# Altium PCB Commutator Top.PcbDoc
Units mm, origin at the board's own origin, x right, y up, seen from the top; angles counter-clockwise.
Board outline 60.27 x 62.49 mm, 2 copper layers (Top, Bottom); 20 components, 31 nets, 112 pads, 44 vias.
Unrouted connection lines stored in the file: 12.
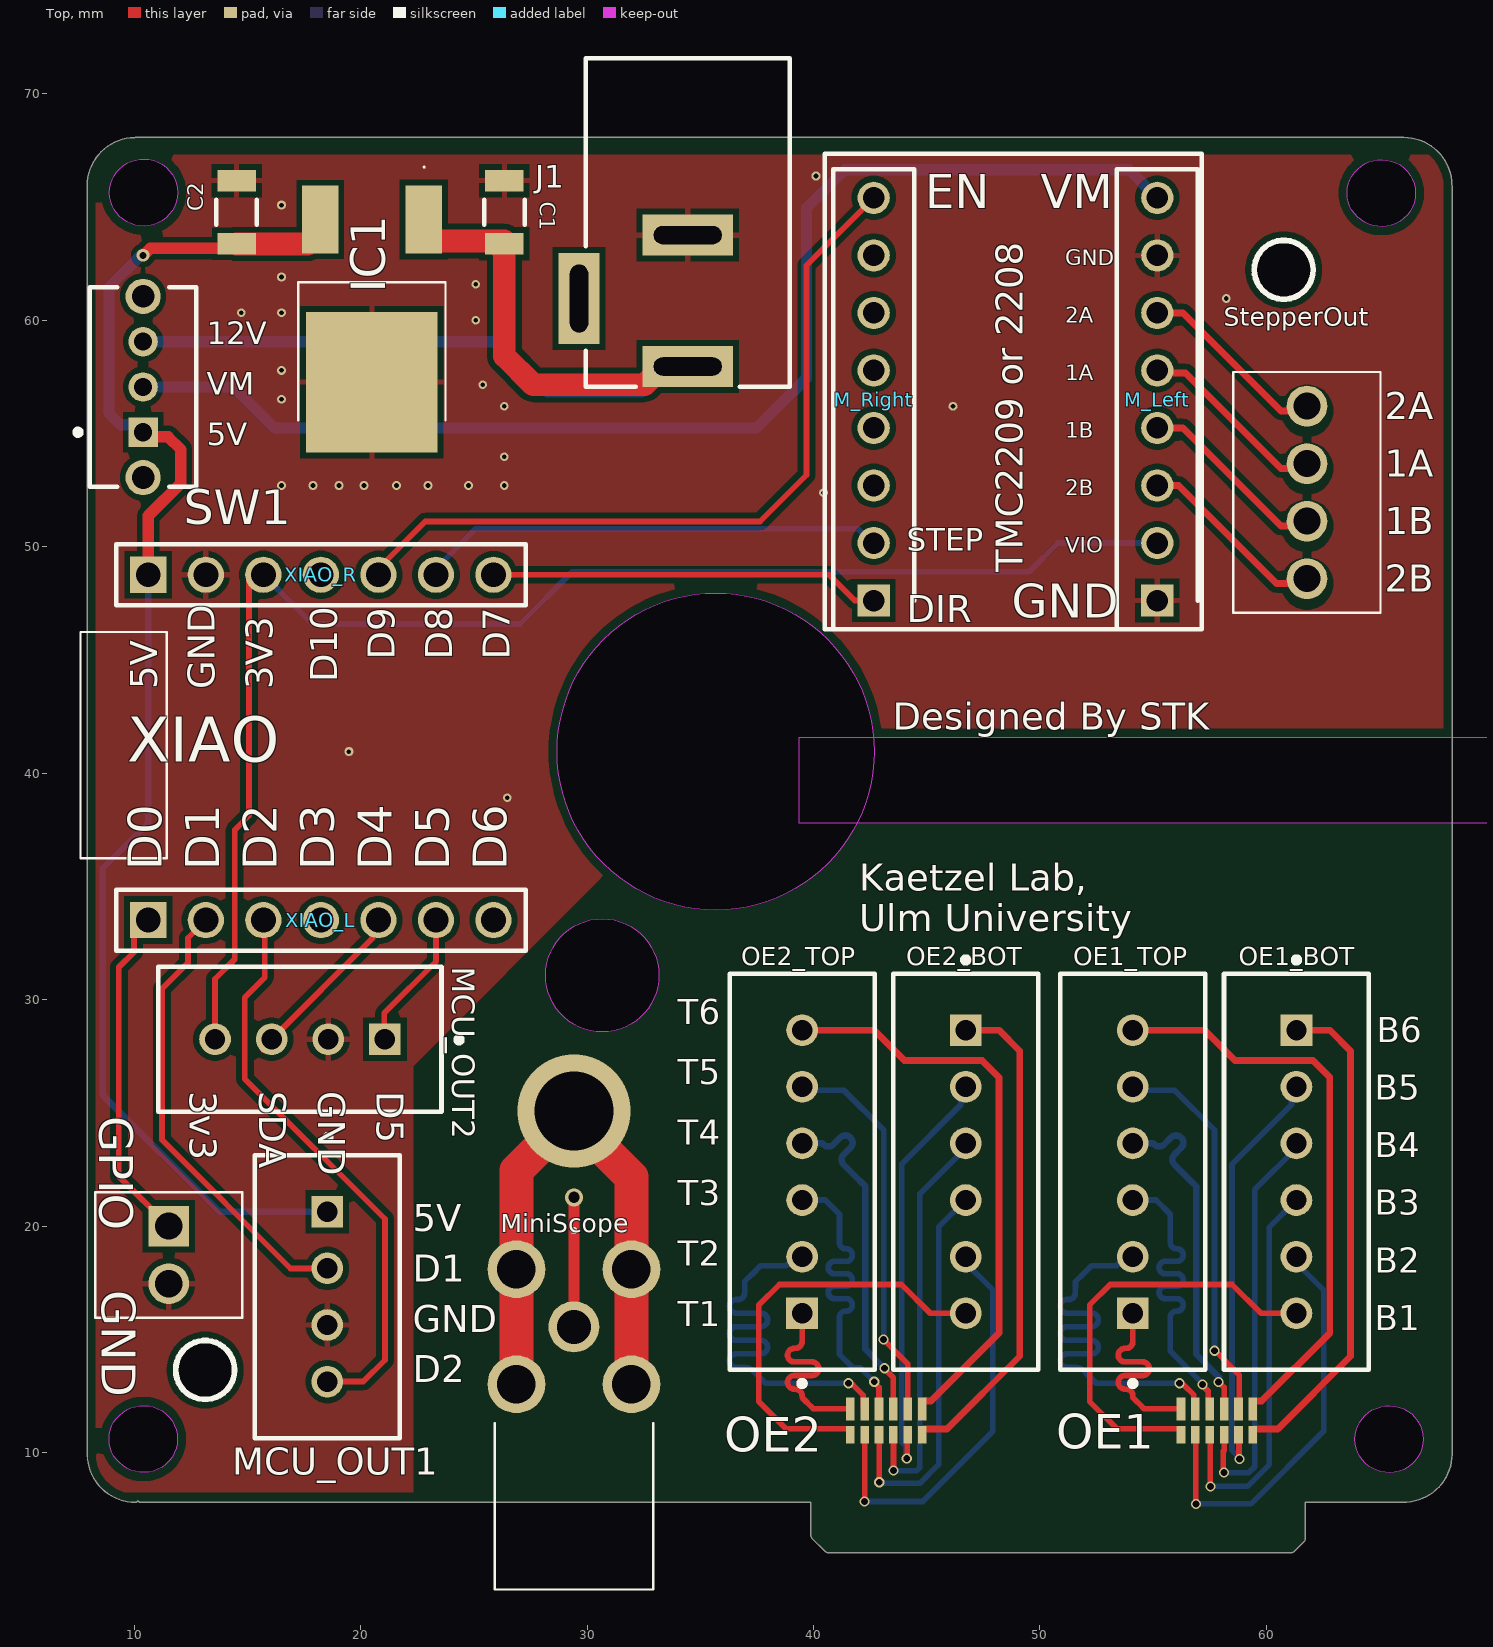
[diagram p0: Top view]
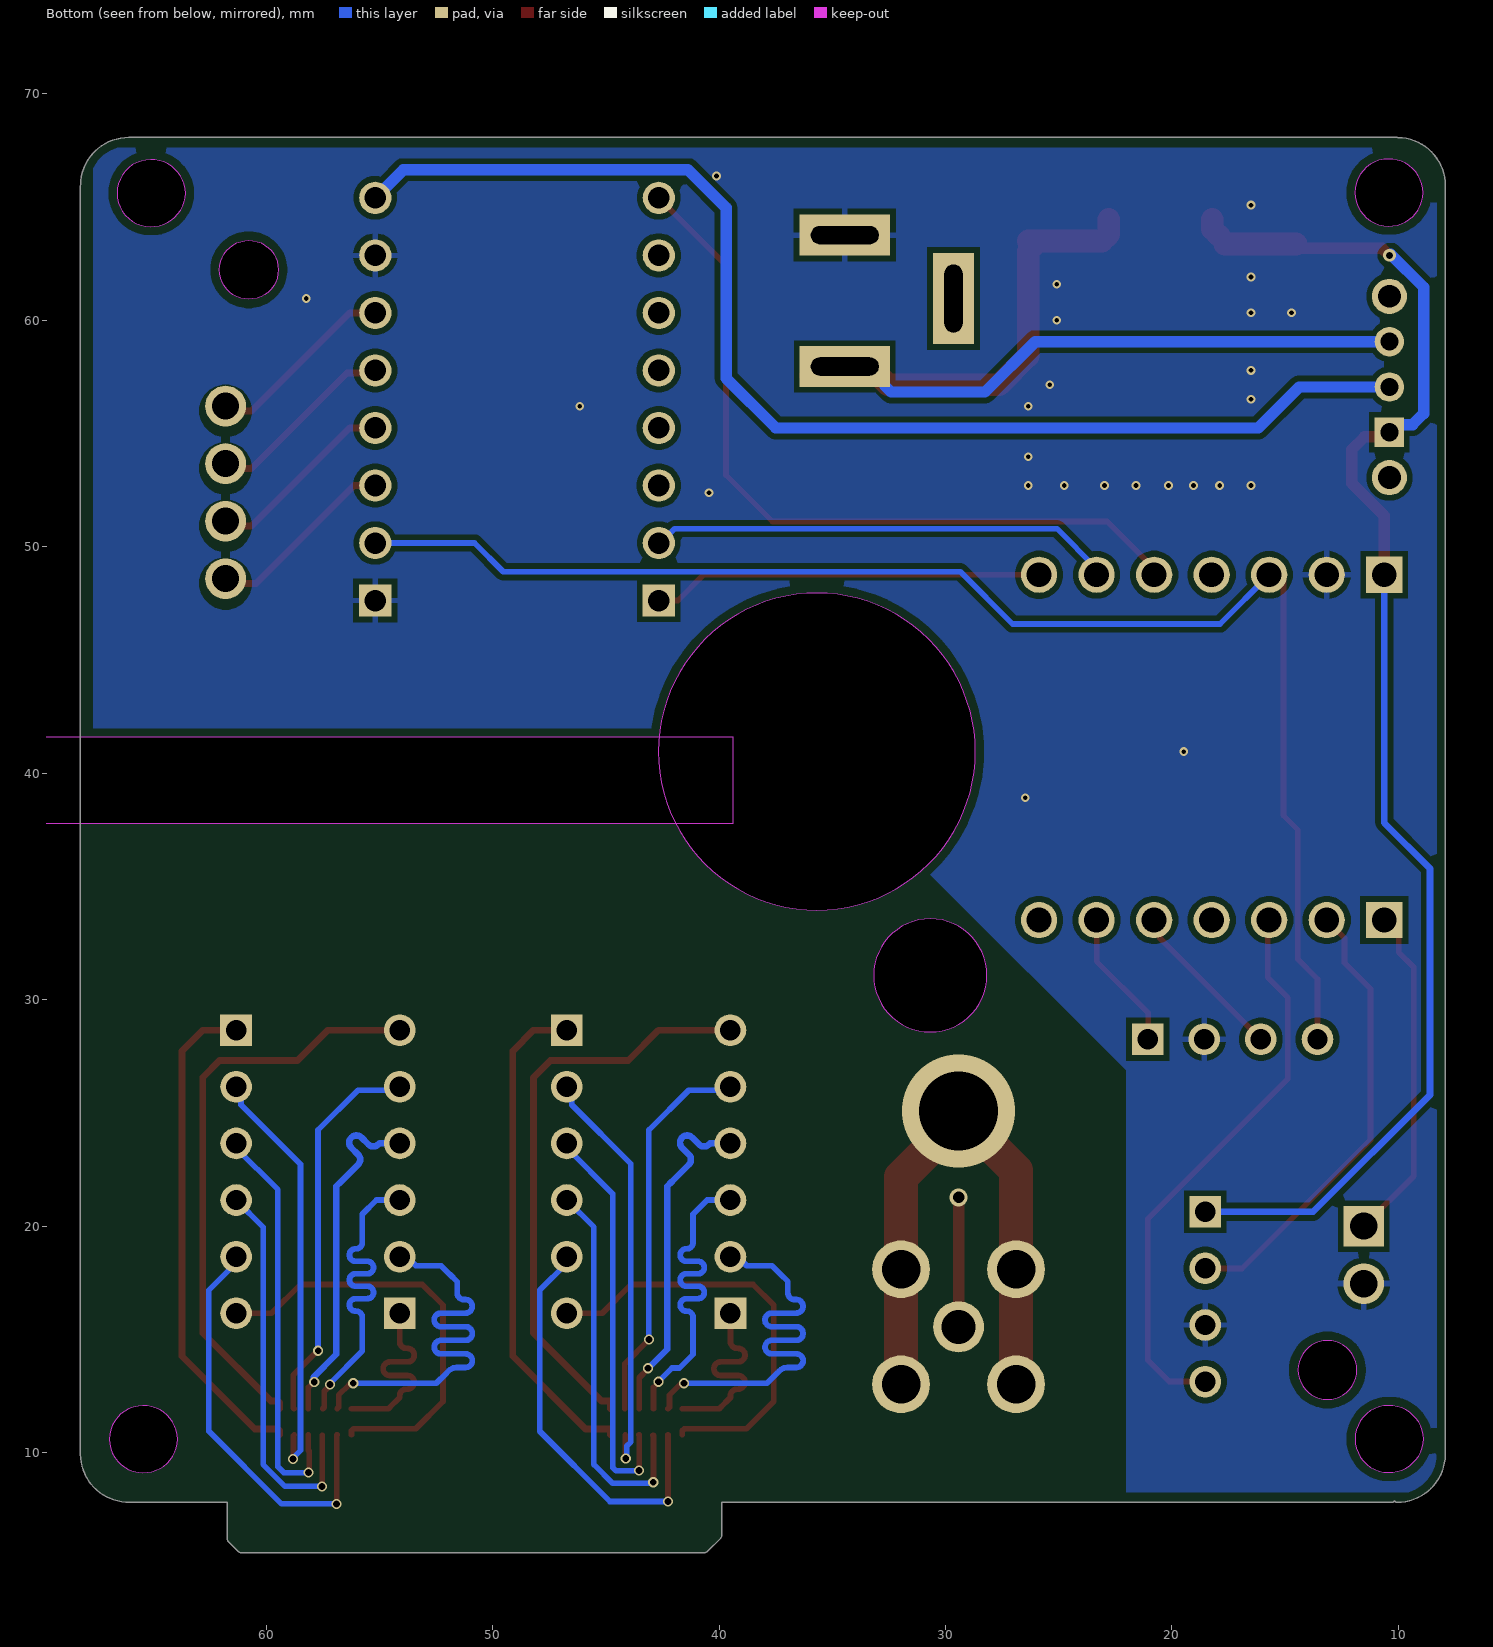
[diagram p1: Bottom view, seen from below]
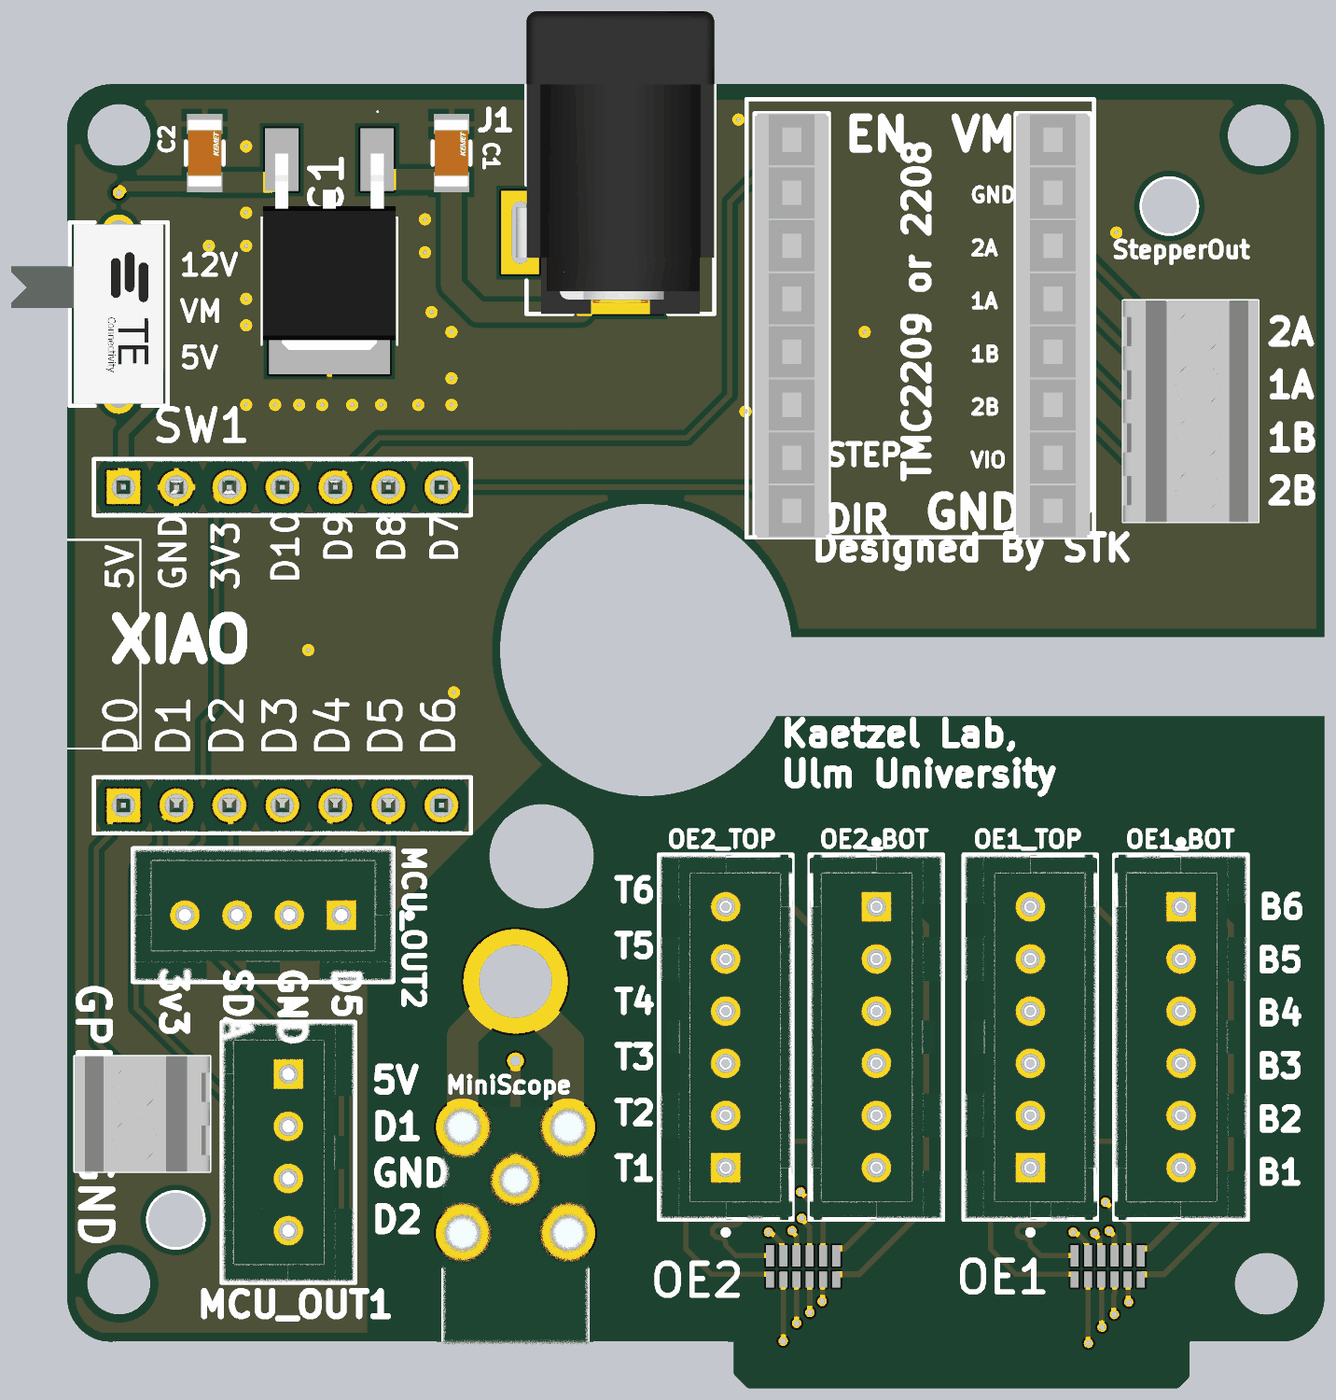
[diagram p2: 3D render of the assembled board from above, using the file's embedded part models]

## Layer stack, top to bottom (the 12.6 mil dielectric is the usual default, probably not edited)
Top Solder: solder mask 0.0102, Solder Resist, Dk 3.5
Top: signal copper 0.035
Dielectric 1: dielectric 0.32, FR-4, Dk 4.8
Bottom: signal copper 0.035
Bottom Solder: solder mask 0.0102, Solder Resist, Dk 3.5

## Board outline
10.059,7.807 ccw(c10.06,7.935) 10.171,7.873 ccw(c10.28,7.938) 10.28,7.81 39.878,7.81 39.878,6.329 39.915,6.239 40.529,5.625 40.619,5.588 61.129,5.588 61.219,5.625 61.685,6.091 61.722,6.181 61.722,7.81 66.16,7.81 66.202,7.817 ccw(c66.068,9.94) 68.195,9.939 68.195,65.942 68.19,65.98 ccw(c66.063,65.948) 66.064,68.075 10.061,68.075 10.023,68.069 ccw(c10.055,65.942) 7.928,65.943 7.928,9.94 7.933,9.903 ccw(c10.061,9.935)
cut-out: 65.442,9.119 cw(c65.407,10.63) 63.895,10.595 cw(c65.407,10.56) 65.442,12.072 cw(c65.442,10.595) 66.918,10.595 cw(c65.442,10.595)
cut-out: 65.103,64.138 cw(c65.068,65.65) 63.557,65.615 cw(c65.068,65.58) 65.103,67.092 cw(c65.103,65.615) 66.58,65.615 cw(c65.103,65.615)
cut-out: 10.448,64.163 cw(c10.413,65.674) 8.902,65.639 cw(c10.413,65.604) 10.448,67.116 cw(c10.448,65.639) 11.925,65.639 cw(c10.448,65.639)
cut-out: 10.44,9.128 cw(c10.405,10.639) 8.894,10.604 cw(c10.405,10.57) 10.44,12.081 cw(c10.44,10.604) 11.917,10.604 cw(c10.44,10.604)
cut-out: 13.138,12.353 cw(c13.138,13.652) 11.838,13.652 cw(c13.138,13.652) 13.138,14.952 cw(c13.138,13.652) 14.438,13.652 cw(c13.138,13.652)
cut-out: 59.463,62.23 ccw(c60.763,62.23) 60.763,60.93 ccw(c60.763,62.23) 62.063,62.23 ccw(c60.763,62.23) 60.763,63.53 ccw(c60.763,62.23)
cut-out: 35.68,33.957 cw(c35.68,40.957) 28.68,40.957 cw(c35.68,40.957) 35.68,47.958 cw(c35.68,40.957) 42.68,40.957 cw(c35.68,40.957)
cut-out: 30.672,28.576 cw(c30.672,31.076) 28.172,31.076 cw(c30.672,31.076) 30.672,33.576 cw(c30.672,31.076) 33.172,31.076 cw(c30.672,31.076)
cut-out: 69.85,37.782 39.37,37.782 39.37,41.593 69.85,41.593

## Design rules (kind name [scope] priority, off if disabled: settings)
BoardOutlineClearance mdCopperDimension [All] p1: gap=0.254 ignorepadtopadclearanceinfootprint=FALSE except(0: Arc-SplitContinuation Track-SplitContinuation SMDPad-SplitContinuation THPad-SplitContinuation Via-SplitContinuation Fill-SplitContinuation Poly-SplitContinuation Region-SplitContinuation Text-SplitContinuation; 0.381: Poly-OutlineEdge Poly-CavityEdge Poly-CutoutEdge Poly-SplitBarrior)
Clearance [All] p1: gap=0.254 ignorepadtopadclearanceinfootprint=FALSE except(0.12: Arc-Arc Arc-Track Track-Track; 0.127: SMDPad-SMDPad; 0.2: Arc-SMDPad Track-SMDPad; 0.33: Arc-THPad Track-THPad; 0.5: THPad-THPad)
DiffPairsRouting DiffPair_USB_QFNDiffPairsRouting [InDifferentialPair ('D')] p1: maxlimit=0.203 minlimit=0.203 mostfreqgap=0.203 toplayer_minwidth=0.174 toplayer_maxwidth=0.174 toplayer_prefwidth=0.174 bottomlayer_minwidth=0.174 bottomlayer_maxwidth=0.174 bottomlayer_prefwidth=0.174 impedanceprofiledriven=TRUE impedanceprofileid={9F019F1D-46EA-4781-B448-3B7AC8F5AEFF} maxuncoupledlength=12.7
DiffPairsRouting DiffPair_USB_QFN_MCUDiffPairsRouting [InDifferentialPair ('VUSB_D')] p2: maxlimit=0.203 minlimit=0.203 mostfreqgap=0.203 toplayer_minwidth=0.174 toplayer_maxwidth=0.174 toplayer_prefwidth=0.174 bottomlayer_minwidth=0.174 bottomlayer_maxwidth=0.174 bottomlayer_prefwidth=0.174 impedanceprofiledriven=TRUE impedanceprofileid={9F019F1D-46EA-4781-B448-3B7AC8F5AEFF} maxuncoupledlength=12.7
DiffPairsRouting [All] p3: maxlimit=0.254 minlimit=0.226 mostfreqgap=0.226 toplayer_minwidth=0.381 toplayer_maxwidth=0.381 toplayer_prefwidth=0.381 bottomlayer_minwidth=0.381 bottomlayer_maxwidth=0.381 bottomlayer_prefwidth=0.381 maxuncoupledlength=12.7
HoleSize HoleSize_For_NetClass_power [InNetClass('power')] p1: absolutevalues=TRUE maxlimit=0 minlimit=0 maxpercent=80.000 minpercent=20.000
HoleSize HoleSize_For_NetClass_thick [InNetClass('thick')] p2: absolutevalues=TRUE maxlimit=0 minlimit=0 maxpercent=80.000 minpercent=20.000
HoleSize [All] p3: absolutevalues=TRUE maxlimit=2540 minlimit=0.381 maxpercent=80.000 minpercent=20.000
HoleToHoleClearance mdDrill [All] p1: gap=0.381 allowstackedmicrovias=TRUE
MinimumSolderMaskSliver [All] p1 off: minsoldermaskwidth=0.254
PasteMaskExpansion mlMinCreamFrame [All] p1: expansion=0
PolygonConnect ThermalVias [IsVia] p1: connectstyle=Direct reliefconductorwidth=0.254 reliefentries=4 polygonreliefangle="90 Angle" airgapwidth=0.254
PolygonConnect [All] p2: connectstyle=Relief reliefconductorwidth=0.254 reliefentries=4 polygonreliefangle="90 Angle" airgapwidth=0.254
RoutingVias RoutingVias_1 [All] p1: holewidth=0.711 width=1.27 viastyle="Through Hole" minholewidth=0.711 minwidth=1.27 maxholewidth=0.711 maxwidth=1.27
RoutingVias [All] p2: holewidth=0.305 width=0.508 viastyle="Through Hole" minholewidth=0.203 minwidth=0.381 maxholewidth=0.711 maxwidth=1.27 useviatemplates=TRUE
SolderMaskExpansion mlMinStopFrame [All] p1: expansion=0.102 istentingtop=FALSE
UnRoutedNet [All] p1: checkbadconnections=TRUE
Width PWR [InNetClass('PWR')] p1: maxlimit=2.54 minlimit=0.203 preferedwidth=0.254 bottomlayer_minwidth=0.254 minimp=50.000000 maximp=50.000000 favimp=50.000000
Width [All] p2: maxlimit=3 minlimit=0.127 preferedwidth=0.127 minimp=50.000000 maximp=50.000000 favimp=50.000000
24 further rules are at their usual default settings.

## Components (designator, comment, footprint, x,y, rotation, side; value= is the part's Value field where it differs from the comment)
C1 "" FP-C1206C-EH-MFG 26.352,64.77 r90 top
C2 "" FP-C1206C-EH-MFG 14.524,64.77 r90 top
GPIO "282834-2" 282834-2_1 11.531,20.002 r270 top
IC1 "MC7805BDTRKG" LM317MADTRKG 20.503,60.372 r90 top
J1 "694106301002" 694106301002 34.448,64.31 r180 top
M_Left "5-535541-6" RHDR8W76P0X254_1X8_2032X356X673P 55.18,47.625 r90 top
M_Right "5-535541-6" RHDR8W76P0X254_1X8_2032X356X673P 42.66,47.625 r90 top
MCU_OUT1 "B04B-XASK-1(LF)(SN)" FP-B04B-XASK-1_LF_SN-MFG 18.535,16.888 r90 top
MCU_OUT2 "B04B-XASK-1(LF)(SN)" FP-B04B-XASK-1_LF_SN-MFG 17.325,28.258 r0 top
MiniScope "132136RP" 132136RP 29.423,15.557 r270 top
OE1 "RHD2000-CABLE-DAQ-SIDE" RHD2000_EVAL_BOARD_OMNETICS_PZN-12-AA 57.814,9.779 r180 top
OE1_BOT "B06B-XASK-1(LF)(SN)" FP-B06B-XASK-1_LF_SN-MFG 61.325,22.405 r90 top
OE1_TOP "B06B-XASK-1(LF)(SN)" FP-B06B-XASK-1_LF_SN-MFG 54.102,22.405 r270 top
OE2 "RHD2000-CABLE-DAQ-SIDE" RHD2000_EVAL_BOARD_OMNETICS_PZN-12-AA 43.209,9.779 r180 top
OE2_BOT "B06B-XASK-1(LF)(SN)" FP-B06B-XASK-1_LF_SN-MFG 46.72,22.405 r90 top
OE2_TOP "B06B-XASK-1(LF)(SN)" FP-B06B-XASK-1_LF_SN-MFG 39.497,22.405 r270 top
StepperOut "282834-4" 2828344 61.789,48.592 r90 top
SW1 "1825232-1" FP-1825232-1-MFG 10.399,57.055 r90 top
XIAO_L "61300711121" 61300711121 18.248,33.514 r0 top
XIAO_R "61300711121" 61300711121 18.248,48.763 r0 top

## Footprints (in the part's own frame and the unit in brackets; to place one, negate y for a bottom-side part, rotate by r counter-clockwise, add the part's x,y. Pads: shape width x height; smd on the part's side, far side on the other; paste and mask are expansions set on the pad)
132136RP [mm]
  round 2.25 hole 1.5: 1(0,0)
  round 2.55 hole 1.7: 2(-2.54,-2.54) 3(2.54,-2.54) 4(2.54,2.54) 5(-2.54,2.54)
  silkscreen extent -4.3,-3.5 11.6,3.5, body extent -3.5,-3.5 11.6,3.5, height 9.96
282834-2_1 [mm]
  rect 1.8x1.8 hole 1.2: 1(0,0)
  round 1.8 hole 1.2: 2(2.54,0)
  silkscreen extent -1.5,-3.25 4.04,3.25, body extent -1.5,-3.25 4.04,3.25, height 9.87
2828344 [mm]
  round 1.8 hole 1.2: 1(0,0) 2(2.54,0) 3(5.08,0) 4(7.62,0)
  silkscreen extent -1.5,-3.25 9.12,3.25, body extent -1.5,-3.25 9.12,3.25, height 9.93
61300711121 [mm] "Pin Header, pitch 2.54 mm, THT, Vertical, single row, 7p"
  rect 1.6x1.6 hole 1.1: 1(-7.62,0)
  round 1.6 hole 1.1: 2(-5.08,0) 3(-2.54,0) 4(0,0) 5(2.54,0) 6(5.08,0) 7(7.62,0)
  silkscreen extent -9.04,-1.35 9.04,1.34, body extent -8.89,-1.27 8.89,1.27, height 8.57
694106301002 [mm] "DC Power Jack Right Angled(6.4)"
  rect 4x1.8 hole 0.8 slot 3 at 0 deg: 1(0,6.35) 2(0,0.55)
  rect 1.8x4 hole 0.8 slot 3 at 90 deg: 3(4.8,3.35)
  silkscreen extent -4.5,-7.25 4.5,7.25, body extent -4.5,-7.25 5,7.25, height 10.75
FP-1825232-1-MFG [mm]
  rect 1.3x1.3 hole 0.8 paste-1000 mask+0: 1(-2,0)
  round 1.3 hole 0.8 paste-1000 mask+0: 2(0,0) 3(2,0)
  round 1.55 hole 1 paste-1000 mask+0: 4(-4,0) 5(4,0)
  silkscreen extent -4.4,-2.35 4.4,3, body extent -4.88,-5.45 4.87,2.45, height 0.25
FP-B04B-XASK-1_LF_SN-MFG [mm]
  rect 1.4x1.4 hole 0.9 paste-1000 mask+0: 1(3.75,0)
  round 1.4 hole 0.9 paste-1000 mask+0: 2(1.25,0) 3(-1.25,0) 4(-3.75,0)
  silkscreen extent -6.25,-3.2 7.15,3.2, body extent -6.35,-3.3 6.35,3.3, height 0.25
FP-B06B-XASK-1_LF_SN-MFG [mm]
  rect 1.4x1.4 hole 0.9 paste-1000 mask+0: 1(6.25,0)
  round 1.4 hole 0.9 paste-1000 mask+0: 2(3.75,0) 3(1.25,0) 4(-1.25,0) 5(-3.75,0) 6(-6.25,0)
  silkscreen extent -8.75,-3.2 9.47,3.2, body extent -8.85,-3.3 8.85,3.3, height 0.25
FP-C1206C-EH-MFG [mm]
  rect 0.95x1.7 smd paste+0 mask+0: 1(-1.4,0) 2(1.4,0)
  silkscreen extent -0.55,-0.9 0.55,0.9, body extent -2,-1 2,1, height 0.25
LM317MADTRKG [mm]
  rect 3x1.6 smd: 1(4.08,-2.285) 3(4.08,2.285)
  rect 6.2x5.8 smd: 2(-3.1,0)
  silkscreen extent -4.79,-3.25 6.43,3.25, body extent -5.03,-3.17 4.37,3.18, height 2.18
RHD2000_EVAL_BOARD_OMNETICS_PZN-12-AA [mil]
  rect 15x30 smd: B1(62.5,-40) B2(37.5,-40) B3(12.5,-40) B4(-12.5,-40) B5(-37.5,-40) B6(-62.5,-40)
  rect 15x40 smd: T1(62.5,-85) T2(37.5,-85) T3(12.5,-85) T4(-12.5,-85) T5(-37.5,-85) T6(-62.5,-85)
RHDR8W76P0X254_1X8_2032X356X673P [mm]
  rect 1.425x1.425 hole 0.95: 1(0,0)
  round 1.425 hole 0.95: 2(2.54,0) 3(5.08,0) 4(7.62,0) 5(10.16,0) 6(12.7,0) 7(15.24,0) 8(17.78,0)
  silkscreen extent -1.27,-1.78 19.05,1.78, body extent -1.27,-1.78 19.05,1.78, height 6.73

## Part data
C1 C2: library part CMP-1037-05005-3, "CAP CER 100UF 6.3V X5R 1206", Capacitance=100uF, Case Code (Imperial)=1206, Case Code (Metric)=3216, Dielectric=X5R, Dielectric Material=Ceramic, Max Operating Temperature=85°C, Min Operating Temperature=-55°C, Package Quantity=1, Tolerance=2%, Voltage=6.3V
GPIO: "Connector", Manufacturer_Name="TE Connectivity", Mouser2 Part Number=571-282834-2
IC1: "Integrated Circuit", Manufacturer_Name=onsemi
J1: library part CMP-1502-00188-1, "DC Power Jack Connector WR-DC, Male, Right Angled, THT, 5 A, 24 V", Manufacturer="Wurth Elektronik", Operating Temperature=-40to85degC, Rated Current=5A, Working Voltage=24V
M_Left M_Right StepperOut: "Connector", Manufacturer_Name="TE Connectivity"
MCU_OUT1 MCU_OUT2: library part CMP-17439-000018-1, "CONN HEADER VERT 4POS 2.5MM", Current Rating=3A, Manufacturer=JST, Temperature="-25°C to +85°C", Temperature Range High=+85°C, Temperature Range Low=-25°C, Voltage Rating=250V
MiniScope: "Connector", Manufacturer_Name=Amphenol
OE1 OE2: "Omnetics PZN-12-AA RHD2000 socket - DAQ side"
OE1_BOT OE1_TOP OE2_BOT OE2_TOP: library part CMP-17439-000268-1, "CONN HEADER VERT 6POS 2.5MM", Color=Beige, Contact Resistance=20mR, Current Rating=3A, Flammability Rating="UL94 V-0", Insulation Color=Natural, Insulation Resistance=1GR, Max Operating Temperature=85°C, Max Voltage Rating (AC)=250V, Min Operating Temperature=-25°C
SW1: library part CMP-03405-000001-1, "SWITCH SLIDE SPDT 200MA 30V", Contact Current Rating=0.2A, Contact Resistance=20mΩ, Manufacturer="TE Connectivity", Operating Force=200gf, Temperature="-20°C to +70°C", Temperature Range High=+70°C, Temperature Range Low=-20°C, Voltage Rating Dc=30V
XIAO_L XIAO_R: library part CMP-1502-01074-1, "THT Vertical Pin Header WR-PHD, Pitch 2.54 mm, Single Row, 7 pins", Contact Resistance=20mOhm, Manufacturer="Wurth Elektronik", Operating Temperature=-40to105degC, Rated Current=3A, Withstanding Voltage=500VAC, Working Voltage=250VAC

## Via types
v1: diameter 0.381, hole 0.203, Top to Bottom, 25 vias
v2: diameter 0.45, hole 0.3, Top to Bottom, 16 vias
v3: diameter 0.56, hole 0.3, Top to Bottom, 1 vias
v4: diameter 5, hole 3.5, Top to Bottom, 1 vias
v5: diameter 0.8, hole 0.5, Top to Bottom, 1 vias

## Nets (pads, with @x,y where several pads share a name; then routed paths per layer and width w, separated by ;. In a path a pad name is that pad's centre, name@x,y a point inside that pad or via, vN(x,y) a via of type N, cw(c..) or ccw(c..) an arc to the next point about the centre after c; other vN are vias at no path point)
1A: M_Left.5 StepperOut.3 | length 8.4
  Top w0.3: M_Left.5 55.288,57.676 56.427,57.676 60.642,53.461 StepperOut.3@61.789,53.461
1B: M_Left.4 StepperOut.2 | length 8.4
  Top w0.3: M_Left.4 56.318,55.245 60.642,50.921 StepperOut.2@61.789,50.921
2A: M_Left.6 StepperOut.4 | length 8.4
  Top w0.3: M_Left.6 56.318,60.325 60.642,56.001 StepperOut.4@61.789,56.001
2B: M_Left.3 StepperOut.1 | length 8.4
  Top w0.3: M_Left.3 55.183,52.702 56.124,52.702 60.445,48.381 StepperOut.1@61.789,48.381
3V3: M_Left.2 MCU_OUT2.4 XIAO_R.3 | length 63
  Top w0.254: MCU_OUT2.4 13.575,30.918 14.442,31.785 14.442,37.5 15.073,38.13 XIAO_R.3@15.073,48.763
  Bottom w0.254: XIAO_R.3 17.884,46.587 27.037,46.587 29.345,48.895 49.53,48.895 50.8,50.165 M_Left.2
+5V: C2.1 IC1.3 MCU_OUT1.1 SW1.1 XIAO_R.1 | length 63.1
  Top w0.5: SW1.1 10.602,54.852 11.506,54.852 12.065,54.292 12.065,52.805 10.628,51.368 XIAO_R.1 ; v3(10.399,62.865) 10.404,62.865 10.721,63.182 14.336,63.182 C2.1 ; IC1.3@17.668,63.37 18.218,63.92 IC1.3
  Top w1: C2.1 IC1.3@17.668,63.37 ; IC1.3@17.918,63.728 18.218,64.027 IC1.3
  Bottom w0.3: XIAO_R.1 10.628,37.813 8.613,35.798 8.613,25.797 13.773,20.637 MCU_OUT1.1
  Bottom w0.5: v3@10.345,62.918 8.89,61.463 8.89,55.88 9.376,55.394 10.06,55.394 SW1.1
A_B1: OE1.B1 OE1_BOT.6 OE2.B1 OE2_BOT.6 | length 38.1
  Top w0.25: OE2.B1 41.621,10.969 41.532,11.058 38.789,11.058 37.586,12.262 37.586,16.517 38.497,17.428 43.88,17.428 45.153,16.155 OE2_BOT.6 ; OE1.B1 56.226,10.969 56.137,11.058 53.394,11.058 52.191,12.262 52.191,16.517 53.102,17.428 58.485,17.428 59.758,16.155 OE1_BOT.6
A_B2: OE1.B2 OE1_BOT.5 OE2.B2 OE2_BOT.5 | length 36.3
  Top w0.25: v2(42.252,7.846) 42.256,7.85 OE2.B2 ; OE1.B2 56.875,10.781 56.875,7.752 v2(56.889,7.739)
  Bottom w0.25: v2(42.252,7.846) 44.822,7.846 47.919,10.943 47.919,17.177 46.72,18.376 OE2_BOT.5 ; v2(56.889,7.739) 59.32,7.739 62.524,10.943 62.524,17.177 61.325,18.376 OE1_BOT.5
A_B3: OE1.B3 OE1_BOT.4 OE2.B3 OE2_BOT.4 | length 34.7
  Top w0.203: OE2.B3 OE2.B3@42.913,10.773 ; OE1.B3 OE1.B3@57.518,10.773
  Top w0.25: v2(42.903,8.697) 42.897,8.703 42.897,10.757 OE2.B3@42.913,10.773 ; OE1.B3@57.518,10.773 57.516,10.77 57.516,8.531 v2(57.535,8.511)
  Bottom w0.25: v2(42.903,8.697) 42.942,8.659 43.083,8.659 43.096,8.646 44.69,8.646 45.525,9.481 45.525,19.96 OE2_BOT.4@46.71,21.145 ; v2(57.535,8.511) 59.161,8.511 60.13,9.481 60.13,19.96 OE1_BOT.4@61.315,21.145
A_B4: OE1.B4 OE1_BOT.3 OE2.B4 OE2_BOT.3 | length 36.2
  Top w0.203: OE2.B4 OE2.B4@43.535,10.786 ; OE1.B4 OE1.B4@58.14,10.786
  Top w0.25: v2(43.531,9.218) 43.529,9.22 43.529,10.78 OE2.B4@43.535,10.786 ; v2(58.127,9.125) 58.093,9.159 58.093,10.06 58.14,10.107 OE1.B4@58.14,10.786
  Bottom w0.25: v2(43.531,9.218) 43.554,9.195 44.545,9.195 44.691,9.342 44.691,21.429 46.72,23.458 OE2_BOT.3 ; v2@58.141,9.111 59.214,9.111 59.481,9.378 59.481,21.614 61.325,23.458 OE1_BOT.3
A_B5: OE1.B5 OE1_BOT.2 OE2.B5 OE2_BOT.2 | length 37.6
  Top w0.203: OE2.B5@44.148,10.782 OE2.B5 ; OE1.B5@58.753,10.782 OE1.B5
  Top w0.25: v2(44.12,9.744) 44.141,9.765 44.141,10.774 OE2.B5@44.148,10.782 ; OE1.B5@58.753,10.782 58.79,10.746 58.79,9.739 v2(58.813,9.715)
  Bottom w0.25: v2(44.12,9.744) 44.082,9.782 44.082,10.282 43.894,10.469 43.894,22.753 46.5,25.36 46.5,25.936 OE2_BOT.2 ; v2(58.813,9.715) 58.813,9.77 58.481,10.102 58.481,22.735 61.105,25.36 61.105,25.936 OE1_BOT.2
A_B6: OE1.B6 OE1_BOT.1 OE2.B6 OE2_BOT.1 | length 44.2
  Top w0.3: OE2.B6 44.796,10.983 44.86,11.046 45.895,11.046 49.106,14.258 49.106,27.737 48.189,28.655 OE2_BOT.1 ; OE1.B6 59.401,10.983 59.465,11.046 60.5,11.046 63.711,14.258 63.711,27.737 62.794,28.655 OE1_BOT.1
A_T1: OE1.T1 OE1_TOP.1 OE2.T1 OE2_TOP.1 | length 18.1
  Top w0.25: OE2_TOP.1 39.497,15.876 39.497,14.908 cw(c39.197,14.908) 39.197,14.608 39.154,14.608 ccw(c39.154,14.308) 39.154,14.008 39.928,14.008 cw(c39.928,13.708) 39.928,13.408 39.154,13.408 ccw(c39.154,13.108) 39.154,12.808 39.197,12.808 cw(c39.197,12.508) 39.497,12.508 39.497,12.434 39.548,12.383 39.916,12.014 39.992,11.938 OE2.T1 ; OE1_TOP.1 54.102,15.876 54.102,14.908 cw(c53.802,14.908) 53.802,14.608 53.759,14.608 ccw(c53.759,14.308) 53.759,14.008 54.533,14.008 cw(c54.533,13.708) 54.533,13.408 53.759,13.408 ccw(c53.759,13.108) 53.759,12.808 53.802,12.808 cw(c53.802,12.508) 54.102,12.508 54.102,12.434 54.153,12.383 54.521,12.014 54.597,11.938 OE1.T1
A_T2: OE1.T2 OE1_TOP.2 OE2.T2 OE2_TOP.2 | length 39.6
  Top w0.25: v2(41.55,13.064) 41.591,13.064 41.666,12.989 41.741,12.989 42.191,12.539 42.191,12.003 OE2.T2 ; v2(56.155,13.064) 56.196,13.064 56.271,12.989 56.346,12.989 56.796,12.539 56.796,12.003 OE1.T2
  Bottom w0.25: 37.288,17.88 36.961,17.553 36.96,17.428 36.96,17.062 cw(c36.66,17.062) 36.66,16.762 36.591,16.762 ccw(c36.591,16.462) 36.591,16.162 37.672,16.162 cw(c37.672,15.862) 37.672,15.562 36.589,15.562 ccw(c36.589,15.262) 36.589,14.962 37.67,14.962 cw(c37.67,14.662) 37.67,14.362 36.587,14.362 ccw(c36.587,14.062) 36.587,13.762 36.971,13.762 cw(c36.971,13.25) 37.333,13.612 37.458,13.487 37.882,13.064 v2(41.55,13.064) ; 37.293,17.88 37.667,18.254 38.779,18.254 39.18,18.655 OE2_TOP.2 ; 51.893,17.88 51.566,17.553 51.565,17.428 51.565,17.062 cw(c51.265,17.062) 51.265,16.762 51.196,16.762 ccw(c51.196,16.462) 51.196,16.162 52.277,16.162 cw(c52.277,15.862) 52.277,15.562 51.194,15.562 ccw(c51.194,15.262) 51.194,14.962 52.275,14.962 cw(c52.275,14.662) 52.275,14.362 51.192,14.362 ccw(c51.192,14.062) 51.192,13.762 51.576,13.762 cw(c51.576,13.25) 51.938,13.612 52.063,13.487 52.487,13.064 v2(56.155,13.064) ; 51.898,17.88 52.272,18.254 53.384,18.254 53.785,18.655 OE1_TOP.2
A_T3: OE1.T3 OE1_TOP.3 OE2.T3 OE2_TOP.3 | length 30.6
  Top w0.25: v2(42.678,13.136) 42.678,13.095 42.891,12.882 OE2.T3 ; v2(57.182,13.012) 57.182,12.958 57.431,12.709 57.431,12.004 OE1.T3
  Bottom w0.25: OE2_TOP.3 40.518,21.155 41.148,20.524 41.148,19.401 41.148,19.276 ccw(c41.423,19.276) 41.423,19.001 41.443,19.001 cw(c41.443,18.726) 41.718,18.726 cw(c41.443,18.726) 41.443,18.451 40.927,18.451 ccw(c40.927,18.176) 40.652,18.176 ccw(c40.927,18.176) 40.927,17.901 41.443,17.901 cw(c41.443,17.626) 41.718,17.626 cw(c41.443,17.626) 41.443,17.351 40.927,17.351 ccw(c40.927,17.076) 40.652,17.076 ccw(c40.927,17.076) 40.927,16.801 41.443,16.801 cw(c41.443,16.526) 41.718,16.526 cw(c41.443,16.526) 41.443,16.251 41.423,16.251 ccw(c41.423,15.976) 41.148,15.976 41.148,15.292 41.148,14.34 41.753,13.736 42.078,13.736 v2(42.678,13.136) ; OE1_TOP.3 55.123,21.155 55.753,20.524 55.753,19.401 55.753,19.276 ccw(c56.028,19.276) 56.028,19.001 56.048,19.001 cw(c56.048,18.726) 56.323,18.726 cw(c56.048,18.726) 56.048,18.451 55.532,18.451 ccw(c55.532,18.176) 55.257,18.176 ccw(c55.532,18.176) 55.532,17.901 56.048,17.901 cw(c56.048,17.626) 56.323,17.626 cw(c56.048,17.626) 56.048,17.351 55.532,17.351 ccw(c55.532,17.076) 55.257,17.076 ccw(c55.532,17.076) 55.532,16.801 56.048,16.801 cw(c56.048,16.526) 56.323,16.526 cw(c56.048,16.526) 56.048,16.251 56.028,16.251 ccw(c56.028,15.976) 55.753,15.976 55.753,15.292 55.753,14.489 57.182,13.061 v2(57.182,13.012)
A_T4: OE1.T4 OE1_TOP.4 OE2.T4 OE2_TOP.4 | length 31.2
  Top w0.25: v2(43.137,13.731) 43.137,13.696 43.526,13.307 43.526,12.882 OE2.T4 ; v2(57.877,13.123) 57.89,13.123 58.131,12.882 OE1.T4
  Bottom w0.285: OE2_TOP.4 39.603,23.761 39.692,23.672 40.29,23.672 40.382,23.672 40.437,23.618 ccw(c40.661,23.842) 40.886,23.618 ; 40.886,23.618 41.183,23.915 cw(c41.407,23.69) 41.632,23.915 cw(c41.407,23.69) 41.632,23.466 41.335,23.169 ccw(c41.56,22.944) 41.335,22.72 41.998,22.057 42.099,21.956 42.292,21.763 42.292,14.566 v2@43.126,13.731 ; OE1_TOP.4 54.208,23.761 54.297,23.672 54.895,23.672 54.987,23.672 55.042,23.618 ccw(c55.266,23.842) 55.491,23.618 ; 55.491,23.618 55.788,23.915 cw(c56.012,23.69) 56.237,23.915 cw(c56.012,23.69) 56.237,23.466 55.94,23.169 ccw(c56.165,22.944) 55.94,22.72 56.603,22.057 56.704,21.956 56.897,21.763 56.897,14.343 57.906,13.334 57.906,13.152 v2(57.877,13.123)
A_T5: OE1.T5 OE1_TOP.5 OE2.T5 OE2_TOP.5 | length 34.3
  Top w0.25: v2(43.088,14.996) 44.161,13.923 OE2.T5 ; v2@57.721,14.504 58.805,13.421 58.805,11.977 OE1.T5
  Bottom w0.25: OE2_TOP.5 39.647,26.005 41.339,26.005 43.099,24.244 43.099,15.008 v2(43.088,14.996) ; OE1_TOP.5 54.252,26.005 55.944,26.005 57.704,24.244 v2@57.704,14.508
  other v2: 57.701,14.504
A_T6: OE1.T6 OE1_TOP.6 OE2.T6 OE2_TOP.6 | length 51.6
  Top w0.3: OE2_TOP.6 42.667,28.655 44.01,27.312 47.45,27.312 48.192,26.569 48.192,15.284 45.186,12.278 44.86,12.278 44.796,12.214 OE2.T6 ; OE1_TOP.6 57.272,28.655 58.615,27.312 62.055,27.312 62.797,26.569 62.797,15.284 59.791,12.278 59.465,12.278 59.401,12.214 OE1.T6
D0: GPIO.1 XIAO_L.1 | length 14.7
  Top w0.254: XIAO_L.1@9.993,33.514 9.993,32.098 9.328,31.432 9.328,22.206 GPIO.1
D1: MCU_OUT1.2 XIAO_L.2 | length 20.2
  Top w0.254: XIAO_L.2 12.383,32.729 12.383,31.63 11.233,30.48 11.233,23.812 16.908,18.138 MCU_OUT1.2
D2: MCU_OUT1.4 XIAO_L.3 | length 25.3
  Top w0.254: XIAO_L.3 15.775,33.447 15.775,30.985 14.891,30.1 14.891,26.505 21.075,20.32 21.075,14.09 20.123,13.138 MCU_OUT1.4
D4_SDA: MCU_OUT2.3 XIAO_L.5 | length 7.4
  Top w0.254: MCU_OUT2.3@15.718,27.784 MCU_OUT2.3@15.854,27.92 ; MCU_OUT2.3 20.53,32.713 20.53,33.257 XIAO_L.5
D5_SCL: MCU_OUT2.1 XIAO_L.6 | length 6.2
  Top w0.254: MCU_OUT2.1 21.047,28.286 21.047,29.409 23.328,31.69 XIAO_L.6
D7_DIR: M_Right.1 XIAO_R.7 | length 17.7
  Top w0.254: XIAO_R.7@25.597,48.763 XIAO_R.7 40.68,48.763 41.818,47.625 M_Right.1@42.862,47.625
D8_STEP: M_Right.2 XIAO_R.6 | length 20.6
  Bottom w0.254: XIAO_R.6 23.328,49.046 25.082,50.8 41.959,50.8 42.594,50.165 M_Right.2
D9_EN: M_Right.8 XIAO_R.5 | length 34.4
  Top w0.254: XIAO_R.5 20.788,49.046 22.86,51.117 37.635,51.117 39.688,53.17 39.688,62.427 M_Right.8@42.662,65.402
GND: C1.2 C2.2 GPIO.2 IC1.2 J1.2 M_Left.1 M_Left.7 MCU_OUT1.3 MCU_OUT2.2 XIAO_R.2
  other v1: 26.473,38.926 19.488,40.957 40.443,52.387 16.51,52.705 17.9,52.705 19.05,52.705 20.153,52.705 21.59,52.705 22.98,52.705 24.765,52.705 26.352,52.705 26.352,53.975 26.352,56.197 46.158,56.197 16.51,56.515 25.4,57.15 16.51,57.785 25.082,60.008 14.725,60.325 16.51,60.325 58.223,60.96 25.082,61.595 16.51,61.912 16.51,65.087 40.111,66.372
GND_miniscope: MiniScope.2 MiniScope.3 MiniScope.4 MiniScope.5 | length 26.2
  Top w1.5: MiniScope.3 MiniScope.2 26.883,22.454 29.423,24.994 v4(29.423,25.082) 29.423,24.704 31.963,22.164 MiniScope.5 MiniScope.4
SIG: MiniScope.1 | length 5.4
  Top w0.5: MiniScope.1@29.423,15.62 v5@29.423,21.016
  other v5: 29.423,21.273
V_IN: C1.1 IC1.1 J1.1 SW1.3 | length 45.6
  Top w1: IC1.1 22.788,63.8 23.088,63.5 C1.1@26.352,63.5 ; C1.1@26.06,63.345 26.352,63.052 26.352,58.42 27.622,57.15 32.538,57.15 33.348,57.96 J1.1 35.548,57.96 J1.1@35.948,57.56
  Bottom w0.5: SW1.3 26.035,59.055 28.258,56.832 32.405,56.832 32.698,57.125 32.698,57.31 33.348,57.96 J1.1
VM: M_Left.8 SW1.2 | length 55.2
  Bottom w0.5: SW1.2 14.382,57.055 16.193,55.245 37.49,55.245 39.688,57.443 39.688,64.967 41.368,66.647 53.937,66.647 M_Left.8
pads on no net: J1.3 M_Right.3 M_Right.4 M_Right.5 M_Right.6 M_Right.7 SW1.4 SW1.5 XIAO_L.4 XIAO_L.7 XIAO_R.4

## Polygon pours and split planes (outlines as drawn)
GND on Bottom "NONET_L04_P-001" (solid, pour order 0): 8.245,67.627 67.627,67.627 67.627,41.91 34.41,41.91 34.41,39.258 22.028,26.876 22.028,8.255 7.627,8.255
GND on Top "NONET_L04_P-001" (solid, remove dead copper, pour order 1): 8.245,67.31 67.848,67.31 67.848,41.755 34.702,41.755 34.702,39.453 22.319,27.071 22.319,8.255 7.63,8.255

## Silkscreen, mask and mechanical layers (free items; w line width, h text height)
Top Overlay:
  circle w0.254: c13.138,13.652 r1.3
  circle w0.254: c60.763,62.23 r1.3
  lines w0.1: 7.634,36.241 7.634,46.241 11.444,46.241 11.444,36.241 7.634,36.241
  lines w0.2: 40.489,46.351 57.152,46.351 57.152,67.351 40.489,67.351 40.489,46.351
  text "EN" at 44.94,64.952 h1.5
  text "VM" at 50.03,64.952 h1.5
  text "GND" at 51.12,62.43 h0.7
  text "2A" at 51.12,59.89 h0.7
  text "12V" at 13.217,58.937 h1
  text "1A" at 51.12,57.35 h0.7
  text "VM" at 13.217,56.715 h1
  text "2A" at 65.226,55.631 h1.2
  text "1B" at 51.12,54.81 h0.7
  text "5V" at 13.217,54.492 h1
  text "1A" at 65.226,53.091 h1.2
  text "2B" at 51.12,52.27 h0.7
  text "1B" at 65.226,50.551 h1.2
  text "STEP" at 44.115,49.83 h1
  text "VIO" at 51.12,49.73 h0.7
  text "TMC2209 or 2208" at 49.23,48.877 h1.2 r90
  text "2B" at 65.226,48.011 h1.2
  text "GND" at 48.76,46.855 h1.5
  text "DIR" at 44.115,46.669 h1.2
  text "D9" at 21.51,45.015 h1.2 r90
  text "D8" at 24.05,45.015 h1.2 r90
  text "D7" at 26.59,45.015 h1.2 r90
  text "D10" at 18.97,44.015 h1.2 r90
  text "5V" at 11.033,43.697 h1.2 r90
  text "GND" at 13.573,43.697 h1.2 r90
  text "3V3" at 16.113,43.697 h1.2 r90
  text "Designed By STK" at 43.497,41.91 h1.2
  text "XIAO" at 9.707,40.505 h2
  text "D0" at 11.214,35.713 h1.5 r90
  text "D1" at 13.754,35.713 h1.5 r90
  text "D2" at 16.293,35.713 h1.5 r90
  text "D3" at 18.834,35.713 h1.5 r90
  text "D4" at 21.374,35.713 h1.5 r90
  text "D5" at 23.914,35.713 h1.5 r90
  text "D6" at 26.453,35.713 h1.5 r90
  text "Kaetzel Lab,  / Ulm University" at 42.016,33.02 h1.2
  text "T6" at 33.995,28.926 h1.1
  text "B6" at 64.877,28.124 h1.1
  text "T5" at 33.995,26.259 h1.1
  text "3v3" at 12.465,25.953 h1.2 r270
  text "SDA" at 15.523,25.953 h1.2 r270
  text "GND" at 18.133,25.953 h1.2 r270
  text "D5" at 20.72,25.953 h1.2 r270
  text "B5" at 64.781,25.582 h1.1
  text "T4" at 33.995,23.592 h1.1
  text "B4" at 64.781,23.039 h1.1
  text "T3" at 33.995,20.925 h1.1
  text "B3" at 64.781,20.497 h1.1
  text "5V" at 22.307,19.767 h1.2
  text "T2" at 33.995,18.258 h1.1
  text "B2" at 64.781,17.955 h1.1
  text "D1" at 22.307,17.545 h1.2
  text "GND" at 8.581,17.162 h1.5 r270
  text "T1" at 33.995,15.591 h1.1
  text "B1" at 64.781,15.413 h1.1
  text "GND" at 22.307,15.322 h1.2
  text "D2" at 22.307,13.1 h1.2
Dimension:
  lines w1: 28.172,30.83 28.268,30.347 28.457,29.892 28.73,29.482 29.078,29.134 29.488,28.86 29.943,28.672 30.426,28.576 30.918,28.576 31.401,28.672 31.856,28.86 32.266,29.134 32.614,29.482 32.888,29.892 33.076,30.347 33.172,30.83 33.172,31.076 33.172,31.322 33.076,31.805 32.888,32.26 32.614,32.67 32.266,33.018 31.856,33.291 31.401,33.48 30.918,33.576 30.426,33.576 29.943,33.48 29.488,33.291 29.078,33.018 28.73,32.67 28.457,32.26 28.268,31.805 28.172,31.322 28.172,31.076 28.172,30.83
Mechanical 26:
  circle w0.254: c65.444,11.556 r0.052
  circle w0.254: c35.68,40.841 r7
  circle w0.254: c30.672,31.076 r2.5
  lines w0.254: 8.055,9.94 8.055,65.943 cw(c10.055,65.942) 10.055,67.942 ; 8.061,9.935 ccw(c10.061,9.935) 10.06,7.935 ; 10.061,67.948 66.064,67.948 cw(c66.063,65.948) 68.063,65.948 ; 10.28,7.938 40.005,7.938 40.005,6.329 40.619,5.715 61.129,5.715 61.595,6.181 61.595,7.938 66.16,7.938 ; 66.068,7.94 ccw(c66.068,9.94) 68.068,9.939 68.068,65.942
